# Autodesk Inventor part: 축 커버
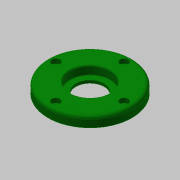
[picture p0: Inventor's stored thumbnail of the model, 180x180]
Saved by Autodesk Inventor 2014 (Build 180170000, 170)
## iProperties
Created: 2015-10
Part Number: 축 커버
Document SubType Name: Modeling
Designer: mdu
Density: 1 g/cm^3
Material: Aluminum 6061
Appearance: Dark Green
Mass: 42.4472 g
Surface Area: 136.578 cm^2
Volume: 42.4472 cm^3
Author: mdu
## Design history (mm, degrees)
sketch "스케치1"
  geometry: C1 r 40 at (0, 0) reference; C2 r 26 at (0, 0) reference; 1 further point
  node "참조1"
  node "참조2"
extrude "돌출1" new body sketch "스케치1" distance "d0" = 10; taper "d1" = 0 deg
extrude "돌출2" join sketch "스케치1" distance "d2" = 4; taper "d3" = 0 deg
hole "구멍1" diameter "d6" = 27; stored, may be unused: countersink angle "d10" = 90 deg, drill point angle "d12" = 118 deg; dims "d7" = 6, "d8" = 38, "d9" = 8.3, "d11" = 8, "d33" = 10, "d34" = 10
sketch "스케치2"
  geometry: C1 r 20 at (0, 0); 1 further point
  constraints: 1 centre point, 1 coincident
  dimensions: "d13" = 40 diameter of C1
extrude "돌출3" cut sketch "스케치2" distance "d14" = 3; taper "d15" = 0 deg
sketch "스케치3"
  geometry: C1 r 1.621 at (0, 32.5) reference; 1 further point
hole "구멍2" sketch "스케치3" at (0, 32.5) diameter "d16" = 4.5; stored, may be unused: countersink angle "d20" = 90 deg, drill point angle "d22" = 118 deg; dims "d17" = 6, "d18" = 8, "d19" = 4.4, "d21" = 8
fillet "모깎기1" dims "d26" = 3, "d27" = 0.3
chamfer "모따기1" distance "d28" = 1; stored, may be unused: second distance "d29" = 2, angle "d30" = 45 deg
chamfer "모따기2" distance "d31" = 0.8; stored, may be unused: second distance "d32" = 2, angle "d35" = 30 deg
node "솔리드1"
pattern_circular "원형 패턴1" dims angle "d24" = 360 deg
node "참조3"
